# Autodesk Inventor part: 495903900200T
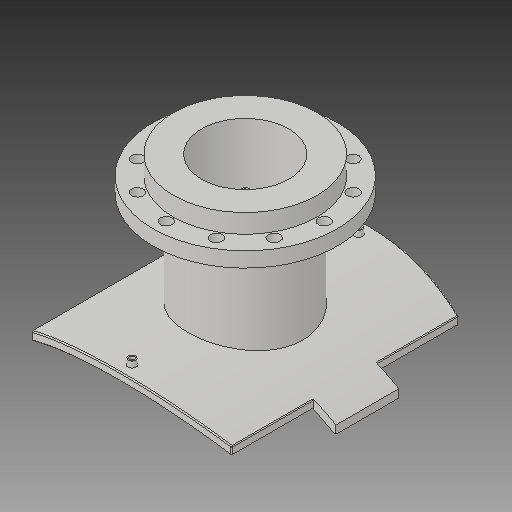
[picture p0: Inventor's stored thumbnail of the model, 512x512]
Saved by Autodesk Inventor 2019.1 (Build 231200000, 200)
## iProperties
Created: 2017-10
Part Number: 495903900200T
Material: Generic
Description: PLASSON FLANGED BRANCH SADDLE 900X200
Document SubType Name: Modeling
Designer: KIM
Mass: 2339.99 g
Surface Area: 3251.55 cm^2
Volume: 2339.99 cm^3
Density: 1 g/cm^3
Appearance: Default
Author: KIM
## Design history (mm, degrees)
derived "495904_495903.ipt"
feature "Solid1::495904_495903.ipt"
feature "Solid2::495904_495903.ipt"
tag "TaggingFeature1"
body "Solid1"
other parameters: "d1" = 15, "d2" = 373.5, "d4" = 0, "d6" = 117.5, "d7" = 0, "d12" = 475.6, "d13" = 14, "d14" = 211.5, "d16" = 5 deg, "d18" = 4, "d19" = 14, "d20" = 0, "d21" = 3, "d22" = 0, "d23" = 715, "d36" = 211.5, "d38" = 0, "d39" = 2, "d41" = 163, "d42" = 268, "d43" = 344, "d46" = 214.4, "d47" = 16, "d48" = 10.4, "d49" = 175, "d51" = 918, "d53" = 0, "d54" = 22, "d55" = 147.5, "d57" = 0, "d59" = 360 deg, "d61" = 28, "d63" = 0, "d67" = 15, "d68" = 125, "d70" = 0, "d71" = 2, "d72" = 415, "d_1" = 268, "B_" = 415, "x_" = 15, "D_" = 16, "DN_" = 163, "D_1" = 344, "t_" = 28, "s_" = 22, "Dp_" = 295
